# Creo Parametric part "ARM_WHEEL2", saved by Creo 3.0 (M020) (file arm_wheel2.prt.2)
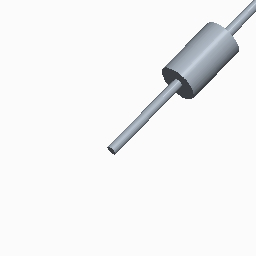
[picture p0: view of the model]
Units: millimeter Newton Second (mmNs); MM, TONNE, SECS

Created from: MMNS_PART_SOLID.PRT

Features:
  1. datum plane "RIGHT"
  2. datum plane "TOP"
  3. datum plane "FRONT"
  4. coordinate system
  5. sketch "Sketch 1"
  6. extrusion "Extrude 1"
  7. sketch "Sketch 2"
  8. extrusion "Extrude 2"
  9. sketch "Sketch 3"
  10. extrusion "Extrude 3"

Surfaces: 7 plane, 6 cylinder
